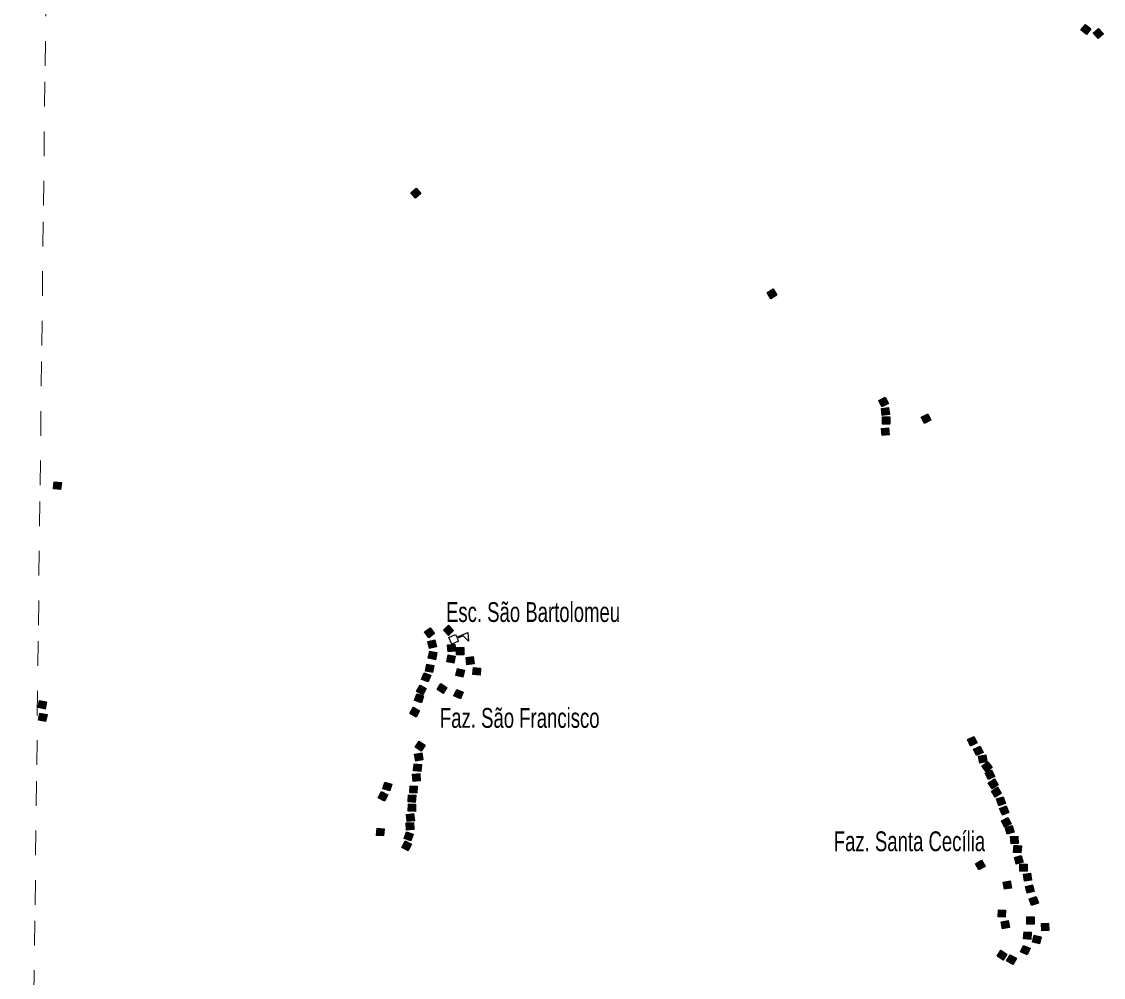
# Model space of a CAD drawing. Extents: x 679 to 705, y 7427.4 to 7455.4.
# Drawn here: x 679.18 to 683.551, y 7443.783 to 7447.645 of the extents above; entities that cross this region are included whole.
import ezdxf

# ---------------------------------------------------------------- set-up
doc = ezdxf.new("R2010")
doc.units = 0
doc.header["$LTSCALE"] = 0.032
doc.linetypes.add('SHORT_DASHED', pattern=[2.7, 1.5, -1.2])
for name, color, linetype, lineweight in [('2', 7, 'Continuous', 25), ('4', 7, 'Continuous', 25), ('58', 7, 'SHORT_DASHED', 13)]:
    doc.layers.add(name, color=color, linetype=linetype, lineweight=lineweight)
doc.layers.add('61', color=7, linetype='Continuous')

msp = doc.modelspace()

# ---------------------------------------------------------------- hatches: boundary and pattern name
at = {"layer": '2'}
for points in [[(683.4791, 7447.634), (683.5012, 7447.6153), (683.4825, 7447.5931), (683.4603, 7447.6118)], [(683.5318, 7447.6174), (683.5513, 7447.596), (683.5299, 7447.5764), (683.5104, 7447.5979)], [(680.7739, 7446.9725), (680.7935, 7446.9512), (680.7722, 7446.9316), (680.7526, 7446.9529)], [(682.2176, 7446.5651), (682.2321, 7446.54), (682.207, 7446.5255), (682.1925, 7446.5506)], [(682.6694, 7446.1273), (682.6824, 7446.1014), (682.6564, 7446.0884), (682.6435, 7446.1143)], [(682.6832, 7446.086), (682.6868, 7446.0572), (682.658, 7446.0536), (682.6544, 7446.0824)], [(682.6882, 7446.0478), (682.6882, 7446.0188), (682.6592, 7446.0188), (682.6592, 7446.0478)], [(682.8414, 7446.0604), (682.8547, 7446.0346), (682.8289, 7446.0213), (682.8156, 7446.0471)], [(682.6837, 7446.0042), (682.6863, 7445.9754), (682.6575, 7445.9727), (682.6548, 7446.0016)], [(679.3408, 7445.783), (679.3377, 7445.7542), (679.3089, 7445.7572), (679.3119, 7445.786)], [(680.8316, 7445.196), (680.8488, 7445.1726), (680.8254, 7445.1554), (680.8082, 7445.1788)], [(680.9057, 7445.2057), (680.9257, 7445.1847), (680.9046, 7445.1647), (680.8847, 7445.1858)], [(680.8501, 7445.1471), (680.8567, 7445.1189), (680.8285, 7445.1122), (680.8218, 7445.1405)], [(680.9304, 7445.1296), (680.9331, 7445.1007), (680.9042, 7445.0981), (680.9015, 7445.127)], [(680.8577, 7445.0952), (680.852, 7445.0668), (680.8235, 7445.0725), (680.8292, 7445.1009)], [(680.9325, 7445.081), (680.9271, 7445.0525), (680.8986, 7445.0579), (680.904, 7445.0864)], [(680.9668, 7445.1157), (680.9668, 7445.0867), (680.9378, 7445.0867), (680.9378, 7445.1157)], [(681.0047, 7445.079), (681.0086, 7445.0503), (680.9798, 7445.0465), (680.976, 7445.0752)], [(680.8181, 7445.0492), (680.8465, 7445.0433), (680.8406, 7445.0149), (680.8122, 7445.0208)], [(681.035, 7445.033), (681.0324, 7445.0041), (681.0035, 7445.0068), (681.0061, 7445.0357)], [(680.8064, 7445.014), (680.8335, 7445.0037), (680.8232, 7444.9766), (680.7961, 7444.9869)], [(680.9698, 7445.0242), (680.9628, 7444.9961), (680.9346, 7445.0031), (680.9417, 7445.0313)], [(680.79, 7444.964), (680.8152, 7444.9498), (680.801, 7444.9245), (680.7757, 7444.9387)], [(680.8989, 7444.9545), (680.8831, 7444.9302), (680.8588, 7444.946), (680.8745, 7444.9703)], [(680.9649, 7444.9351), (680.9532, 7444.9086), (680.9266, 7444.9204), (680.9384, 7444.9469)], [(679.2806, 7444.8959), (679.2751, 7444.8674), (679.2466, 7444.8729), (679.2521, 7444.9014)], [(680.7767, 7444.929), (680.8044, 7444.9202), (680.7956, 7444.8926), (680.768, 7444.9013)], [(680.763, 7444.8747), (680.7882, 7444.8603), (680.7738, 7444.8351), (680.7486, 7444.8495)], [(679.2828, 7444.8454), (679.2773, 7444.8169), (679.2488, 7444.8224), (679.2543, 7444.8509)], [(680.7864, 7444.7378), (680.8107, 7444.722), (680.7949, 7444.6976), (680.7706, 7444.7134)], [(683.0279, 7444.7566), (683.0409, 7444.7307), (683.0149, 7444.7177), (683.002, 7444.7437)], [(680.7968, 7444.6902), (680.8018, 7444.6617), (680.7733, 7444.6566), (680.7682, 7444.6852)], [(683.0529, 7444.7177), (683.0655, 7444.6915), (683.0393, 7444.679), (683.0268, 7444.7052)], [(680.7959, 7444.6437), (680.7931, 7444.6148), (680.7642, 7444.6176), (680.767, 7444.6464)], [(683.0758, 7444.6825), (683.0809, 7444.654), (683.0523, 7444.6489), (683.0473, 7444.6774)], [(683.0843, 7444.6545), (683.1014, 7444.631), (683.0778, 7444.614), (683.0608, 7444.6375)], [(680.7886, 7444.6063), (680.7911, 7444.5774), (680.7622, 7444.5748), (680.7597, 7444.6037)], [(683.0999, 7444.6211), (683.1131, 7444.5952), (683.0872, 7444.5821), (683.0741, 7444.6079)], [(680.6484, 7444.5725), (680.6762, 7444.564), (680.6677, 7444.5363), (680.64, 7444.5447)], [(680.7786, 7444.5562), (680.7776, 7444.5272), (680.7486, 7444.5282), (680.7496, 7444.5572)], [(683.1108, 7444.5848), (683.126, 7444.5601), (683.1013, 7444.5449), (683.0861, 7444.5696)], [(680.6345, 7444.5341), (680.66, 7444.5203), (680.6461, 7444.4948), (680.6206, 7444.5087)], [(680.7726, 7444.5191), (680.7708, 7444.4902), (680.7419, 7444.4919), (680.7436, 7444.5209)], [(683.1235, 7444.5513), (683.1388, 7444.5266), (683.1141, 7444.5113), (683.0988, 7444.536)], [(683.147, 7444.5131), (683.156, 7444.4855), (683.1284, 7444.4765), (683.1194, 7444.504)], [(680.7724, 7444.4826), (680.7711, 7444.4537), (680.7421, 7444.455), (680.7434, 7444.484)], [(683.1583, 7444.4763), (683.1697, 7444.4496), (683.1431, 7444.4382), (683.1317, 7444.4649)], [(680.7635, 7444.4449), (680.7671, 7444.4162), (680.7384, 7444.4126), (680.7348, 7444.4414)], [(683.1652, 7444.4288), (683.1782, 7444.4029), (683.1523, 7444.3899), (683.1393, 7444.4158)], [(680.6452, 7444.3833), (680.6431, 7444.3544), (680.6141, 7444.3565), (680.6162, 7444.3854)], [(680.7631, 7444.4089), (680.7645, 7444.38), (680.7356, 7444.3785), (680.7341, 7444.4075)], [(683.1829, 7444.3971), (683.1908, 7444.3692), (683.163, 7444.3612), (683.155, 7444.3891)], [(680.7559, 7444.3207), (680.7425, 7444.295), (680.7168, 7444.3084), (680.7302, 7444.3341)], [(680.7629, 7444.3614), (680.753, 7444.3341), (680.7258, 7444.344), (680.7357, 7444.3713)], [(683.2056, 7444.3532), (683.2072, 7444.3242), (683.1782, 7444.3226), (683.1766, 7444.3516)], [(683.2203, 7444.3145), (683.2177, 7444.2856), (683.1888, 7444.2882), (683.1914, 7444.3171)], [(683.0594, 7444.2568), (683.0737, 7444.2316), (683.0486, 7444.2172), (683.0342, 7444.2424)], [(683.2196, 7444.2758), (683.2275, 7444.248), (683.1996, 7444.24), (683.1917, 7444.2679)], [(683.243, 7444.2408), (683.243, 7444.2118), (683.214, 7444.2118), (683.214, 7444.2408)], [(683.2568, 7444.2043), (683.2611, 7444.1756), (683.2324, 7444.1713), (683.2281, 7444.2)], [(683.1752, 7444.1726), (683.1799, 7444.144), (683.1513, 7444.1392), (683.1466, 7444.1678)], [(683.2368, 7444.1509), (683.265, 7444.1576), (683.2717, 7444.1294), (683.2435, 7444.1227)], [(683.2795, 7444.1098), (683.289, 7444.0824), (683.2615, 7444.0729), (683.2521, 7444.1004)], [(683.1558, 7444.0552), (683.1548, 7444.0262), (683.1258, 7444.0273), (683.1269, 7444.0563)], [(683.167, 7444.0132), (683.1721, 7443.9846), (683.1436, 7443.9795), (683.1385, 7444.008)], [(683.2717, 7444.027), (683.2717, 7443.998), (683.2427, 7443.998), (683.2427, 7444.027)], [(683.33, 7444.0021), (683.3314, 7443.9731), (683.3025, 7443.9717), (683.3011, 7444.0007)], [(683.2598, 7443.9655), (683.258, 7443.9366), (683.2291, 7443.9383), (683.2308, 7443.9672)], [(683.3003, 7443.9466), (683.2931, 7443.9185), (683.265, 7443.9257), (683.2722, 7443.9538)], [(683.2282, 7443.9123), (683.2549, 7443.9009), (683.2434, 7443.8742), (683.2168, 7443.8856)], [(683.1372, 7443.8925), (683.1616, 7443.8768), (683.1458, 7443.8524), (683.1215, 7443.8682)], [(683.1746, 7443.8747), (683.1997, 7443.8602), (683.1852, 7443.8351), (683.1601, 7443.8496)]]:
    msp.add_hatch(color=256, dxfattribs=at).paths.add_polyline_path(points)

# ---------------------------------------------------------------- linework, layer by layer
for points in [[(683.4791, 7447.634), (683.5012, 7447.6153), (683.4825, 7447.5931), (683.4603, 7447.6118)], [(683.5318, 7447.6174), (683.5513, 7447.596), (683.5299, 7447.5764), (683.5104, 7447.5979)], [(680.7739, 7446.9725), (680.7935, 7446.9512), (680.7722, 7446.9316), (680.7526, 7446.9529)], [(682.2176, 7446.5651), (682.2321, 7446.54), (682.207, 7446.5255), (682.1925, 7446.5506)], [(682.6694, 7446.1273), (682.6824, 7446.1014), (682.6564, 7446.0884), (682.6435, 7446.1143)], [(682.6832, 7446.086), (682.6868, 7446.0572), (682.658, 7446.0536), (682.6544, 7446.0824)], [(682.6882, 7446.0478), (682.6882, 7446.0188), (682.6592, 7446.0188), (682.6592, 7446.0478)], [(682.8414, 7446.0604), (682.8547, 7446.0346), (682.8289, 7446.0213), (682.8156, 7446.0471)], [(682.6837, 7446.0042), (682.6863, 7445.9754), (682.6575, 7445.9727), (682.6548, 7446.0016)], [(679.3408, 7445.783), (679.3377, 7445.7542), (679.3089, 7445.7572), (679.3119, 7445.786)], [(680.8316, 7445.196), (680.8488, 7445.1726), (680.8254, 7445.1554), (680.8082, 7445.1788)], [(680.9057, 7445.2057), (680.9257, 7445.1847), (680.9046, 7445.1647), (680.8847, 7445.1858)], [(680.8501, 7445.1471), (680.8567, 7445.1189), (680.8285, 7445.1122), (680.8218, 7445.1405)], [(680.9304, 7445.1296), (680.9331, 7445.1007), (680.9042, 7445.0981), (680.9015, 7445.127)], [(680.8577, 7445.0952), (680.852, 7445.0668), (680.8235, 7445.0725), (680.8292, 7445.1009)], [(680.9325, 7445.081), (680.9271, 7445.0525), (680.8986, 7445.0579), (680.904, 7445.0864)], [(680.9668, 7445.1157), (680.9668, 7445.0867), (680.9378, 7445.0867), (680.9378, 7445.1157)], [(681.0047, 7445.079), (681.0086, 7445.0503), (680.9798, 7445.0465), (680.976, 7445.0752)], [(680.8181, 7445.0492), (680.8465, 7445.0433), (680.8406, 7445.0149), (680.8122, 7445.0208)], [(681.035, 7445.033), (681.0324, 7445.0041), (681.0035, 7445.0068), (681.0061, 7445.0357)], [(680.8064, 7445.014), (680.8335, 7445.0037), (680.8232, 7444.9766), (680.7961, 7444.9869)], [(680.9698, 7445.0242), (680.9628, 7444.9961), (680.9346, 7445.0031), (680.9417, 7445.0313)], [(680.79, 7444.964), (680.8152, 7444.9498), (680.801, 7444.9245), (680.7757, 7444.9387)], [(680.8989, 7444.9545), (680.8831, 7444.9302), (680.8588, 7444.946), (680.8745, 7444.9703)], [(680.9649, 7444.9351), (680.9532, 7444.9086), (680.9266, 7444.9204), (680.9384, 7444.9469)], [(679.2806, 7444.8959), (679.2751, 7444.8674), (679.2466, 7444.8729), (679.2521, 7444.9014)], [(680.7767, 7444.929), (680.8044, 7444.9202), (680.7956, 7444.8926), (680.768, 7444.9013)], [(680.763, 7444.8747), (680.7882, 7444.8603), (680.7738, 7444.8351), (680.7486, 7444.8495)], [(679.2828, 7444.8454), (679.2773, 7444.8169), (679.2488, 7444.8224), (679.2543, 7444.8509)], [(680.7864, 7444.7378), (680.8107, 7444.722), (680.7949, 7444.6976), (680.7706, 7444.7134)], [(683.0279, 7444.7566), (683.0409, 7444.7307), (683.0149, 7444.7177), (683.002, 7444.7437)], [(680.7968, 7444.6902), (680.8018, 7444.6617), (680.7733, 7444.6566), (680.7682, 7444.6852)], [(683.0529, 7444.7177), (683.0655, 7444.6915), (683.0393, 7444.679), (683.0268, 7444.7052)], [(680.7959, 7444.6437), (680.7931, 7444.6148), (680.7642, 7444.6176), (680.767, 7444.6464)], [(683.0758, 7444.6825), (683.0809, 7444.654), (683.0523, 7444.6489), (683.0473, 7444.6774)], [(683.0843, 7444.6545), (683.1014, 7444.631), (683.0778, 7444.614), (683.0608, 7444.6375)], [(680.7886, 7444.6063), (680.7911, 7444.5774), (680.7622, 7444.5748), (680.7597, 7444.6037)], [(683.0999, 7444.6211), (683.1131, 7444.5952), (683.0872, 7444.5821), (683.0741, 7444.6079)], [(680.6484, 7444.5725), (680.6762, 7444.564), (680.6677, 7444.5363), (680.64, 7444.5447)], [(680.7786, 7444.5562), (680.7776, 7444.5272), (680.7486, 7444.5282), (680.7496, 7444.5572)], [(683.1108, 7444.5848), (683.126, 7444.5601), (683.1013, 7444.5449), (683.0861, 7444.5696)], [(680.6345, 7444.5341), (680.66, 7444.5203), (680.6461, 7444.4948), (680.6206, 7444.5087)], [(680.7726, 7444.5191), (680.7708, 7444.4902), (680.7419, 7444.4919), (680.7436, 7444.5209)], [(683.1235, 7444.5513), (683.1388, 7444.5266), (683.1141, 7444.5113), (683.0988, 7444.536)], [(683.147, 7444.5131), (683.156, 7444.4855), (683.1284, 7444.4765), (683.1194, 7444.504)], [(680.7724, 7444.4826), (680.7711, 7444.4537), (680.7421, 7444.455), (680.7434, 7444.484)], [(683.1583, 7444.4763), (683.1697, 7444.4496), (683.1431, 7444.4382), (683.1317, 7444.4649)], [(680.7635, 7444.4449), (680.7671, 7444.4162), (680.7384, 7444.4126), (680.7348, 7444.4414)], [(683.1652, 7444.4288), (683.1782, 7444.4029), (683.1523, 7444.3899), (683.1393, 7444.4158)], [(680.6452, 7444.3833), (680.6431, 7444.3544), (680.6141, 7444.3565), (680.6162, 7444.3854)], [(680.7631, 7444.4089), (680.7645, 7444.38), (680.7356, 7444.3785), (680.7341, 7444.4075)], [(683.1829, 7444.3971), (683.1908, 7444.3692), (683.163, 7444.3612), (683.155, 7444.3891)], [(680.7559, 7444.3207), (680.7425, 7444.295), (680.7168, 7444.3084), (680.7302, 7444.3341)], [(680.7629, 7444.3614), (680.753, 7444.3341), (680.7258, 7444.344), (680.7357, 7444.3713)], [(683.2056, 7444.3532), (683.2072, 7444.3242), (683.1782, 7444.3226), (683.1766, 7444.3516)], [(683.2203, 7444.3145), (683.2177, 7444.2856), (683.1888, 7444.2882), (683.1914, 7444.3171)], [(683.0594, 7444.2568), (683.0737, 7444.2316), (683.0486, 7444.2172), (683.0342, 7444.2424)], [(683.2196, 7444.2758), (683.2275, 7444.248), (683.1996, 7444.24), (683.1917, 7444.2679)], [(683.243, 7444.2408), (683.243, 7444.2118), (683.214, 7444.2118), (683.214, 7444.2408)], [(683.2568, 7444.2043), (683.2611, 7444.1756), (683.2324, 7444.1713), (683.2281, 7444.2)], [(683.1752, 7444.1726), (683.1799, 7444.144), (683.1513, 7444.1392), (683.1466, 7444.1678)], [(683.2368, 7444.1509), (683.265, 7444.1576), (683.2717, 7444.1294), (683.2435, 7444.1227)], [(683.2795, 7444.1098), (683.289, 7444.0824), (683.2615, 7444.0729), (683.2521, 7444.1004)], [(683.1558, 7444.0552), (683.1548, 7444.0262), (683.1258, 7444.0273), (683.1269, 7444.0563)], [(683.167, 7444.0132), (683.1721, 7443.9846), (683.1436, 7443.9795), (683.1385, 7444.008)], [(683.2717, 7444.027), (683.2717, 7443.998), (683.2427, 7443.998), (683.2427, 7444.027)], [(683.33, 7444.0021), (683.3314, 7443.9731), (683.3025, 7443.9717), (683.3011, 7444.0007)], [(683.2598, 7443.9655), (683.258, 7443.9366), (683.2291, 7443.9383), (683.2308, 7443.9672)], [(683.3003, 7443.9466), (683.2931, 7443.9185), (683.265, 7443.9257), (683.2722, 7443.9538)], [(683.2282, 7443.9123), (683.2549, 7443.9009), (683.2434, 7443.8742), (683.2168, 7443.8856)], [(683.1372, 7443.8925), (683.1616, 7443.8768), (683.1458, 7443.8524), (683.1215, 7443.8682)], [(683.1746, 7443.8747), (683.1997, 7443.8602), (683.1852, 7443.8351), (683.1601, 7443.8496)]]:
    msp.add_lwpolyline(points, close=True, dxfattribs=at)
at = {"layer": '4'}
for points in [[(680.9404, 7445.1527), (680.9453, 7445.1417), (680.9187, 7445.1299), (680.907, 7445.1565), (680.9336, 7445.1682), (680.9384, 7445.1572)], [(680.9384, 7445.1572), (680.9827, 7445.1768), (680.9858, 7445.1411), (680.9643, 7445.1633), (680.9404, 7445.1527)]]:
    msp.add_lwpolyline(points, dxfattribs=at)
at = {"layer": '58'}
msp.add_lwpolyline([(679.1802, 7439.5566), (679.1869, 7440.1216), (679.1937, 7440.6866), (679.2005, 7441.2516), (679.2073, 7441.8166), (679.2141, 7442.3815), (679.2208, 7442.9465), (679.2276, 7443.5115), (679.2344, 7444.0765), (679.2412, 7444.6415), (679.2479, 7445.2065), (679.2547, 7445.7715), (679.2615, 7446.3365), (679.2682, 7446.9015), (679.275, 7447.4665), (679.2818, 7448.0315)], dxfattribs=at)

# ---------------------------------------------------------------- texts
at = {"layer": '61', "width": 0.7}
for s, p in [('Esc. São Bartolomeu', (680.895, 7445.2192)), ('Faz. São Francisco', (680.8704, 7444.7914)), ('Faz. Santa Cecília', (682.4618, 7444.2929))]:
    msp.add_text(s, height=0.08, dxfattribs=at).set_placement(p)

doc.saveas('drawing.dxf')
